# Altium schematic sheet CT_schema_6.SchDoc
size 371 x 243 mm
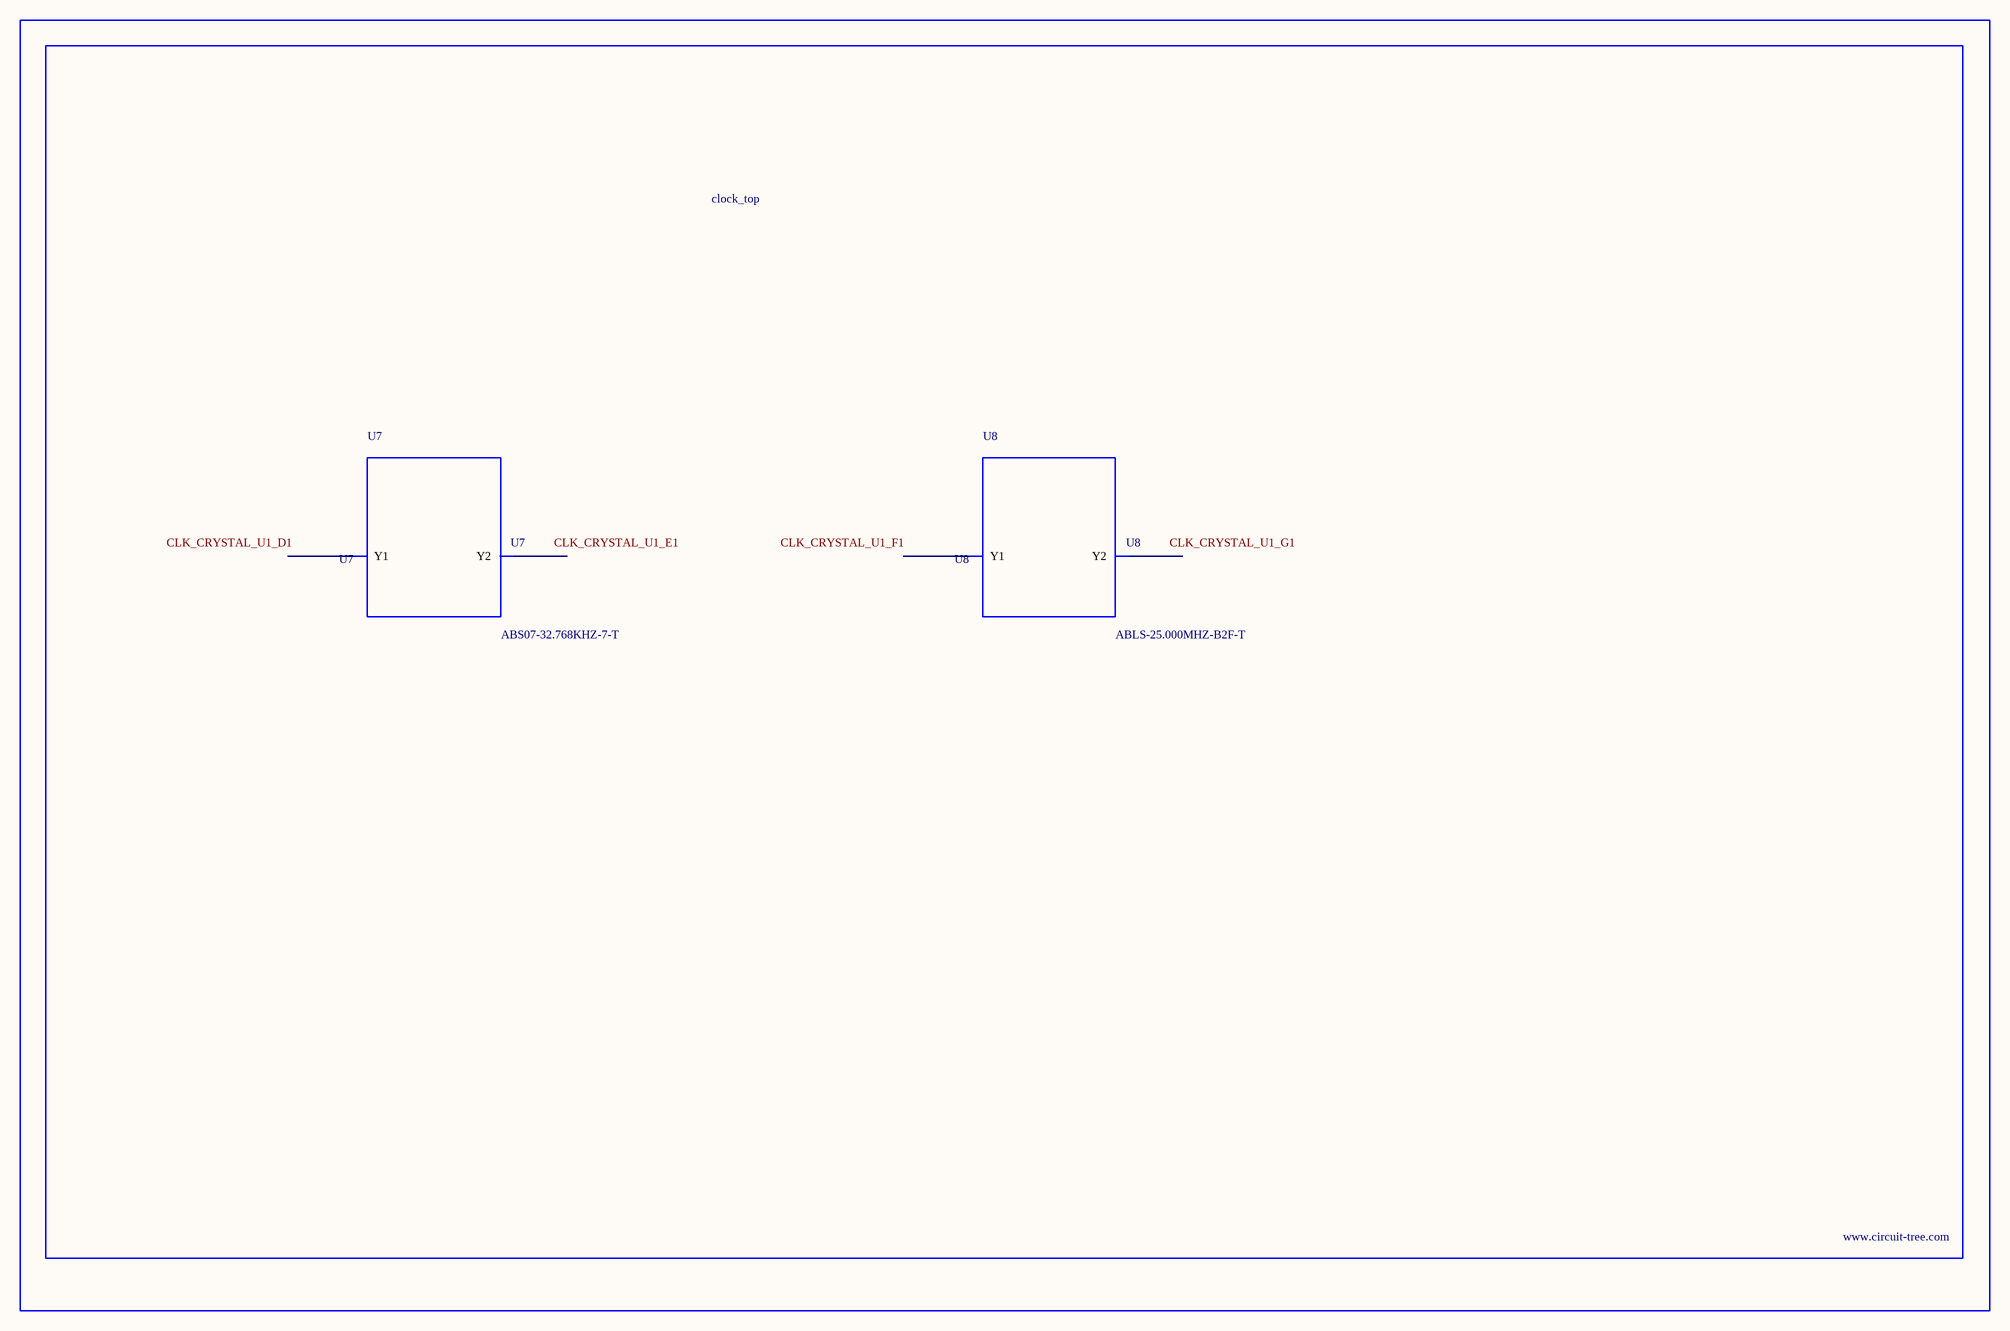
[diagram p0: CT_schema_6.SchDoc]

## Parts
BORDER5  (no value)
U7  ABS07-32.768KHZ-7-T  [ABS07-32.768KHZ-7-T]
U8  ABLS-25.000MHZ-B2F-T  [ABLS-25.000MHZ-B2F-T]

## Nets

Not connected (* = marked no-connect by the designer): U7 1(Y1) 2(Y2); U8 1(Y1) 2(Y2)

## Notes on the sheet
- Labels drawn without touching a wire or pin: CLK_CRYSTAL_U1_D1, CLK_CRYSTAL_U1_E1, CLK_CRYSTAL_U1_F1, CLK_CRYSTAL_U1_G1

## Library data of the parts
BORDER5 = BORDER_PAGE5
